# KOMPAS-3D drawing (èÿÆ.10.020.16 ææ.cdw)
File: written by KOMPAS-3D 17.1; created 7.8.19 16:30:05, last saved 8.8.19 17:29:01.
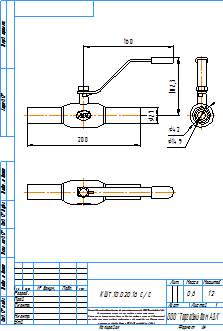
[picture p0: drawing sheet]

Sheet 1: A4, portrait

Title block, sheet 1: name: КШТ.10.020.16 С/С; material: Сталь 20  ГОСТ 1050-2013; mass: 0,6; sheets: 1; sheet format: A4; stored path: C:\Users\kka\KOMPAS_Work\Модели кранов для исследований\DN65\КШТ.10.065.16 СС.cdw

Views: Вид 1, Проекционный вид 2, Проекционный вид 3
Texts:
  kka
  adl
  Рама для чертежей
  Лит-Масса-Масштаб
  Материал-Предприятие
  Масштаб
  Изм.
  Лист
  № докум.
  Подп.
  Дата
  Лит.
  Разраб.
  Пров.
  Т.контр.
  Листов
  Внимание! Данный продукт является объектом авторского права ООО «Торговый Дом АДЛ».
  Запрещается изменение, копирование, распространение
  (в том числе путем копирования на другие сайты и ресурсы в Интернете)
  или любое иное использование информации и объектов без предварительного
  согласия правообладателя (ООО «Торговый Дом АДЛ»).
  Н.контр.
  Утв.
  ООО "Торговый дом АДЛ"
  Изменение
  Номер документа
  Подпись
  Обозначение документа
  Наименование изделия
  Масса изделия по ГОСТ 2.109-73
  Порядковый номер листа
  Общее количество листов в документе
  Характер работы, выполненной лицом, подписавшим документ
  Наименование или индекс предприятия, выпускающего документ
  Инв. № подл.
  Подп. и дата
  Взам. инв. №
  Инв. № дубл.
  Инвентарный номер подлинника по ГОСТ 2.501-68
  Подпись принявшего подлинник в отдел технической документации
  Инвентарный номер подлинника, взамен которого выпущен данный подлинник
  Инвентарный номер дубликата по ГОСТ 2.502-68
  Подпись принявшего дубликат в отдел технической документации
  Справ. №
  Перв. примен.
  Обозначение документа, взамен или на основании которого выпущен данный документ
  Обозначение документа, в котором впервые записан данный документ
  Подпись лица, копировавшего чертеж
  Обозначение формата листа
  !Рама для чертежа
Dimensions and other numbers on the sheet: 160; 102,3; 200; 27; 42; 14,9; 1:2; 1; 0,6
